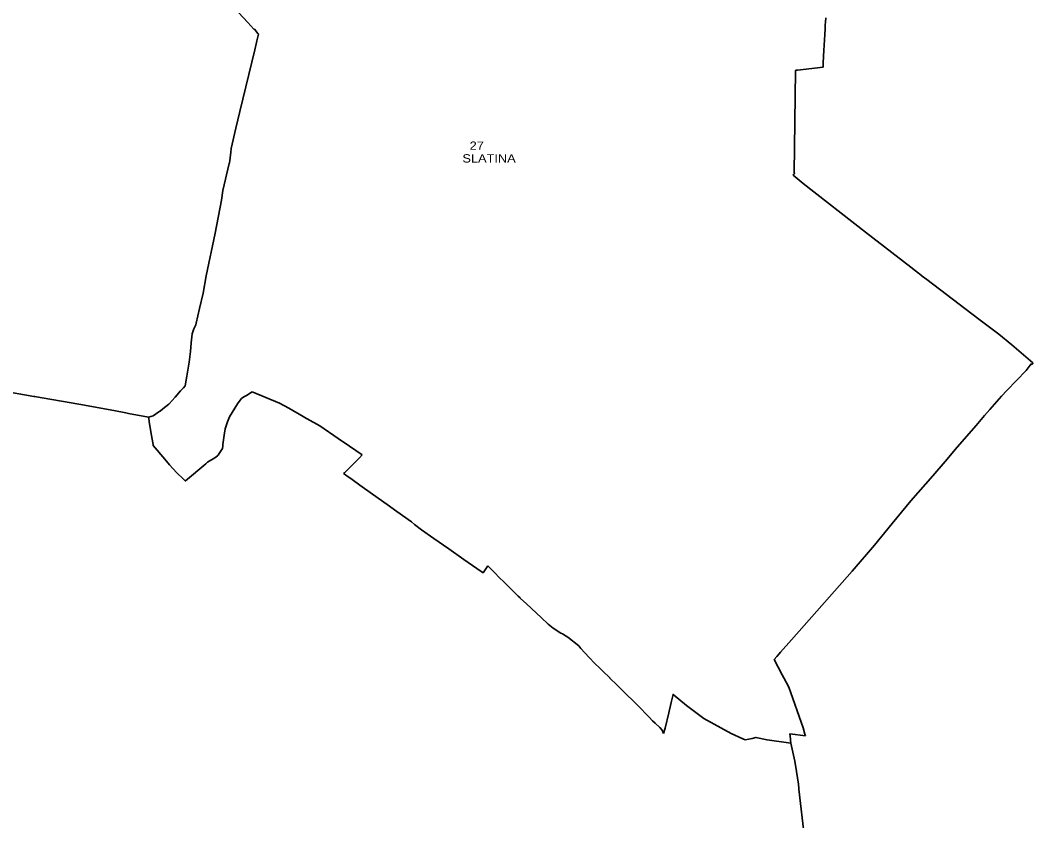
# Model space of a CAD drawing. Extents: x -610940 to -588976, y -1170376 to -1149800.
# Drawn here: x -594465 to -591419, y -1165441 to -1163033 of the extents above; entities that cross this region are included whole.
import ezdxf

# ---------------------------------------------------------------- set-up
doc = ezdxf.new("R2010")
doc.units = 0
doc.header["$LTSCALE"] = 10
doc.layers.add('54', color=7, linetype='Continuous', lineweight=35)
doc.layers.add('55', color=7, linetype='Continuous')
doc.layers.add('56', color=7, linetype='Continuous')

msp = doc.modelspace()

# ---------------------------------------------------------------- linework, layer by layer
at = {"layer": '54'}
for p, q in [((-591423.35, -1164066.76), (-591420.83, -1164069.02)), ((-593784.62, -1164161.37), (-593767.74, -1164150.43)), ((-593684.77, -1164184.98), (-593767.74, -1164150.43)), ((-594184.16, -1164207.24), (-594289.35, -1164187.66)), ((-593657.58, -1164200.36), (-593684.77, -1164184.98)), ((-594147.7, -1164214.03), (-594184.16, -1164207.24)), ((-594139.97, -1164215.46), (-594147.7, -1164214.03)), ((-594079.16, -1164226.78), (-594139.97, -1164215.46)), ((-594045.62, -1164209.3), (-594048.25, -1164211.29)), ((-594044.59, -1164208.76), (-594045.62, -1164209.3)), ((-594036.39, -1164202.01), (-594044.59, -1164208.76)), ((-593835.25, -1164225.64), (-593841.76, -1164241.37)), ((-593848.76, -1164261.69), (-593851.76, -1164281.15)), ((-593841.76, -1164241.37), (-593848.76, -1164261.69)), ((-593856.03, -1164308.68), (-593851.76, -1164281.15)), ((-593490.71, -1164397.71), (-593492.48, -1164396.43)), ((-593091.52, -1164682.16), (-593131, -1164655.33)), ((-593008.22, -1164724.41), (-593024.85, -1164707.89)), ((-592986.42, -1164746.07), (-592993.14, -1164739.39)), ((-592971.12, -1164761.26), (-592973.7, -1164758.7)), ((-592971.12, -1164761.26), (-592966.66, -1164765.69)), ((-592818.12, -1164888.53), (-592822.96, -1164885.34)), ((-592273.03, -1165195.38), (-592284.08, -1165197.91)), ((-592263.52, -1165193.2), (-592273.03, -1165195.38))]:
    msp.add_line(p, q, dxfattribs=at)
for points in [[(-593780.66, -1163040.25), (-593808.88, -1163009.98), (-593846.81, -1162969.29), (-593856.71, -1162959.27), (-593866.98, -1162948.8), (-593873.44, -1162942.33)], [(-593780.66, -1163040.25), (-593762.71, -1163059.72), (-593760.96, -1163060.04), (-593750.15, -1163072.48), (-593748.3, -1163074.72), (-593751.26, -1163087.02), (-593752.29, -1163091.33), (-593753.16, -1163094.96), (-593754.4, -1163100.12), (-593759.76, -1163122.44), (-593804.14, -1163307.29)], [(-592041.88, -1163025.77), (-592042.55, -1163038.53), (-592042.97, -1163046.28), (-592043.62, -1163058.48), (-592044.53, -1163075.65), (-592047.11, -1163124.07), (-592047.99, -1163140.61), (-592049.16, -1163162.52), (-592049.53, -1163169.49)], [(-592132.81, -1163183.82), (-592132.83, -1163185.64), (-592136.3, -1163492), (-592134.85, -1163493.31), (-592137.21, -1163496.08), (-592139.6, -1163498.87), (-592109.57, -1163524.31)], [(-592132.81, -1163183.82), (-592131.55, -1163183.62), (-592126.93, -1163183.07), (-592049.76, -1163173.96), (-592049.72, -1163173.23), (-592049.53, -1163169.49)], [(-593804.14, -1163307.29), (-593816.38, -1163357.7), (-593830.95, -1163418.62), (-593832.17, -1163431.23), (-593833.75, -1163445.72), (-593834.09, -1163448.06), (-593836.1, -1163462.01), (-593836.3, -1163463.42), (-593855.79, -1163544.77), (-593860.06, -1163573.77), (-593878.64, -1163673.2), (-593905.46, -1163802.25), (-593915.21, -1163854.18), (-593925.66, -1163900.36), (-593935.61, -1163944.32), (-593936.8, -1163948.8), (-593940.05, -1163954.8), (-593943.49, -1163961.18), (-593947.91, -1163976.59), (-593951.32, -1164003.56), (-593952.95, -1164029.39), (-593957.54, -1164061.62), (-593961.19, -1164085.31), (-593964.2, -1164103.41), (-593969.47, -1164132.29), (-593974.18, -1164138.75), (-593976.64, -1164141.57), (-593982.77, -1164148.07), (-593999.31, -1164167.18), (-594016.84, -1164186.38), (-594017.93, -1164187.57), (-594036.39, -1164202.01)], [(-592109.57, -1163524.31), (-591922.48, -1163670.8), (-591785.57, -1163775.99), (-591771.46, -1163786.83), (-591762.85, -1163793.44), (-591759.7, -1163795.86), (-591751.07, -1163802.5), (-591737.29, -1163813.08), (-591580.56, -1163931.72)], [(-591580.56, -1163931.72), (-591521, -1163977.16), (-591481.97, -1164009.2), (-591418.79, -1164063.13), (-591419.9, -1164066.34), (-591420.83, -1164069.02)], [(-591423.35, -1164066.76), (-591439.05, -1164086.51), (-591497.04, -1164147.22), (-591512.56, -1164163.47), (-591548.36, -1164204.27), (-591563.85, -1164221.85), (-591578.88, -1164239.83), (-591588.95, -1164251.88), (-591646.51, -1164317.36), (-591682.73, -1164360.18), (-591719.75, -1164403.28), (-591785.31, -1164478.94), (-591842.21, -1164547.25), (-591895.14, -1164611.92), (-591962.38, -1164690.63), (-592030.38, -1164767.36), (-592144.98, -1164896.82)], [(-594289.35, -1164187.66), (-594422.05, -1164164.73), (-594424.62, -1164164.3), (-594526.67, -1164146.81), (-594634.24, -1164127.9), (-594651.29, -1164124.79), (-594679.69, -1164118.66)], [(-593799.18, -1164170.5), (-593809.92, -1164184.3), (-593811.3, -1164186.54), (-593835.25, -1164225.64)], [(-593784.62, -1164161.37), (-593792.46, -1164166.28), (-593799.18, -1164170.5)], [(-593611.69, -1164226.32), (-593614.21, -1164224.89), (-593657.58, -1164200.36)], [(-594048.25, -1164211.29), (-594065.23, -1164223.11), (-594079.16, -1164226.78)], [(-594076.98, -1164240.29), (-594077.35, -1164237.98), (-594078.29, -1164232.25), (-594079.16, -1164226.78)], [(-593508.63, -1164290.85), (-593563.96, -1164253.32), (-593601.71, -1164232.02), (-593611.03, -1164226.69), (-593611.69, -1164226.32)], [(-594065.8, -1164309.4), (-594066.64, -1164304.19), (-594071.95, -1164271.36), (-594076.98, -1164240.29)], [(-593436.4, -1164340.04), (-593474.15, -1164314.24), (-593508.63, -1164290.85)], [(-593994.97, -1164393.04), (-594015.82, -1164370.45), (-594030.58, -1164352.98), (-594065.5, -1164311.75), (-594065.8, -1164309.4)], [(-593857.25, -1164321.01), (-593866.78, -1164336.63), (-593869.66, -1164341.35)], [(-593856.03, -1164308.68), (-593856.19, -1164314.1), (-593857.25, -1164321.01)], [(-593880.3, -1164349.36), (-593901.66, -1164362.67), (-593907.22, -1164366.92)], [(-593869.66, -1164341.35), (-593872.18, -1164343.25), (-593880.3, -1164349.36)], [(-593492.48, -1164396.43), (-593490.05, -1164394.02), (-593465.82, -1164370.81), (-593444.42, -1164348.99), (-593436.4, -1164340.04)], [(-593907.22, -1164366.92), (-593968.31, -1164418.05), (-593968.97, -1164418.6)], [(-593968.97, -1164418.6), (-593974.49, -1164413.17), (-593994.97, -1164393.04)], [(-593490.71, -1164397.71), (-593485.21, -1164401.68), (-593482.58, -1164403.58)], [(-593443.19, -1164431.98), (-593466.9, -1164414.88), (-593482.58, -1164403.58)], [(-593361.68, -1164489.78), (-593405.2, -1164458.75), (-593443.19, -1164431.98)], [(-593287.64, -1164541.85), (-593332.33, -1164510.42), (-593361.68, -1164489.78)], [(-593131, -1164655.33), (-593175.91, -1164623.22), (-593220.91, -1164591.68), (-593258.08, -1164565.44), (-593278.92, -1164550.05), (-593287.64, -1164541.85)], [(-593058.4, -1164674.64), (-593070.61, -1164691.74), (-593072.84, -1164694.86), (-593091.52, -1164682.16)], [(-593024.85, -1164707.89), (-593036.14, -1164696.71), (-593058.4, -1164674.64)], [(-593008.22, -1164724.41), (-592999.42, -1164733.15), (-592996.4, -1164736.16), (-592993.14, -1164739.39)], [(-592986.42, -1164746.07), (-592977.39, -1164755.04), (-592973.7, -1164758.7)], [(-592960.68, -1164771.13), (-592961.14, -1164770.7), (-592966.66, -1164765.69)], [(-592851.04, -1164868.86), (-592861.72, -1164861.76), (-592876.7, -1164849.72), (-592898.4, -1164829.41), (-592942.3, -1164788.33), (-592960.68, -1164771.13)], [(-592838.3, -1164876.4), (-592849.65, -1164869.78), (-592851.04, -1164868.86)], [(-592822.96, -1164885.34), (-592833.94, -1164878.94), (-592838.3, -1164876.4)], [(-592736.31, -1164968.05), (-592753.15, -1164949.61), (-592778.24, -1164922.54), (-592784.95, -1164915.12), (-592818.12, -1164888.53)], [(-592144.98, -1164896.82), (-592177.67, -1164934.1), (-592182.02, -1164939.23), (-592188.95, -1164947.39), (-592196.35, -1164956.11), (-592172.3, -1165001.98), (-592167.44, -1165011.26), (-592153.08, -1165038.66), (-592109.9, -1165161.4), (-592104.09, -1165180.76), (-592102.71, -1165185.35)], [(-592713.69, -1164990.12), (-592721.77, -1164982.23), (-592736.31, -1164968.05)], [(-592691.69, -1165011.25), (-592712.59, -1164991.18), (-592713.69, -1164990.12)], [(-592529.98, -1165178.76), (-592533.92, -1165168.25), (-592541.22, -1165160.92), (-592554.84, -1165147.33), (-592562.54, -1165140.41), (-592573.28, -1165129.13), (-592581.92, -1165120.38), (-592599.3, -1165102.67), (-592616.58, -1165085.16), (-592626.09, -1165075.57), (-592635.83, -1165066.14), (-592645.94, -1165056.24), (-592669.96, -1165032.62), (-592690.89, -1165012.24), (-592691.69, -1165011.25)], [(-592284.08, -1165197.91), (-592290.9, -1165194.42), (-592326.25, -1165178.36), (-592408.85, -1165133.52), (-592461, -1165094.49), (-592500.4, -1165061.34), (-592500.81, -1165061), (-592503.61, -1165072.78), (-592506.57, -1165085.25), (-592513.95, -1165116.37), (-592524.9, -1165162.54), (-592529.98, -1165178.76)], [(-592146.28, -1165207.74), (-592218, -1165198.05), (-592251.83, -1165190.53), (-592263.52, -1165193.2)], [(-592102.71, -1165185.35), (-592149.39, -1165179.7), (-592147.77, -1165194.29), (-592147.29, -1165198.6), (-592146.28, -1165207.74)], [(-592122.19, -1165345.55), (-592122.36, -1165343.59), (-592123.92, -1165331), (-592129.86, -1165292.35), (-592134.95, -1165261.78), (-592146.28, -1165207.74)], [(-592106.01, -1165492.02), (-592122.19, -1165345.55)]]:
    msp.add_lwpolyline(points, dxfattribs=at)

# ---------------------------------------------------------------- texts
at = {"layer": '55', "width": 1.15}
msp.add_text('SLATINA ', height=25, dxfattribs=at).set_placement((-593134.83, -1163460.99))
at = {"layer": '56', "width": 1.15}
msp.add_text('27 ', height=25, dxfattribs=at).set_placement((-593113.08, -1163422.74))

doc.saveas('drawing.dxf')
